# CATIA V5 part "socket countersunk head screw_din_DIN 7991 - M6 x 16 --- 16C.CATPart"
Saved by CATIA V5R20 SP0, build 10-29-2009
Part number: socket countersunk head screw_din_DIN 7991 - M6 x 16 --- 16C
Revision: ANY
Definition: UNKNOWN
Nomenclature: socket countersunk head screw_din_DIN 7991 - M6 x 16 --- 16C
Source: Unknown
Bounding box of the stored display mesh (mm): x 0 to 16, y -5.785 to 5.785, z -5.785 to 5.785
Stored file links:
  C:\Users\Utente\Desktop\IO LAVORO\3D X SITO CF\CUMSA\3D files GR\GR 283432-10\socket countersunk head screw_din_DIN 7991 - M6 x 16 --- 16C.CATPart
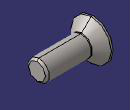
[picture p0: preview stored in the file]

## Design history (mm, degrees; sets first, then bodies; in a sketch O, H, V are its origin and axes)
Body1 "Hex" (main body)
  Solid1: solid without history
